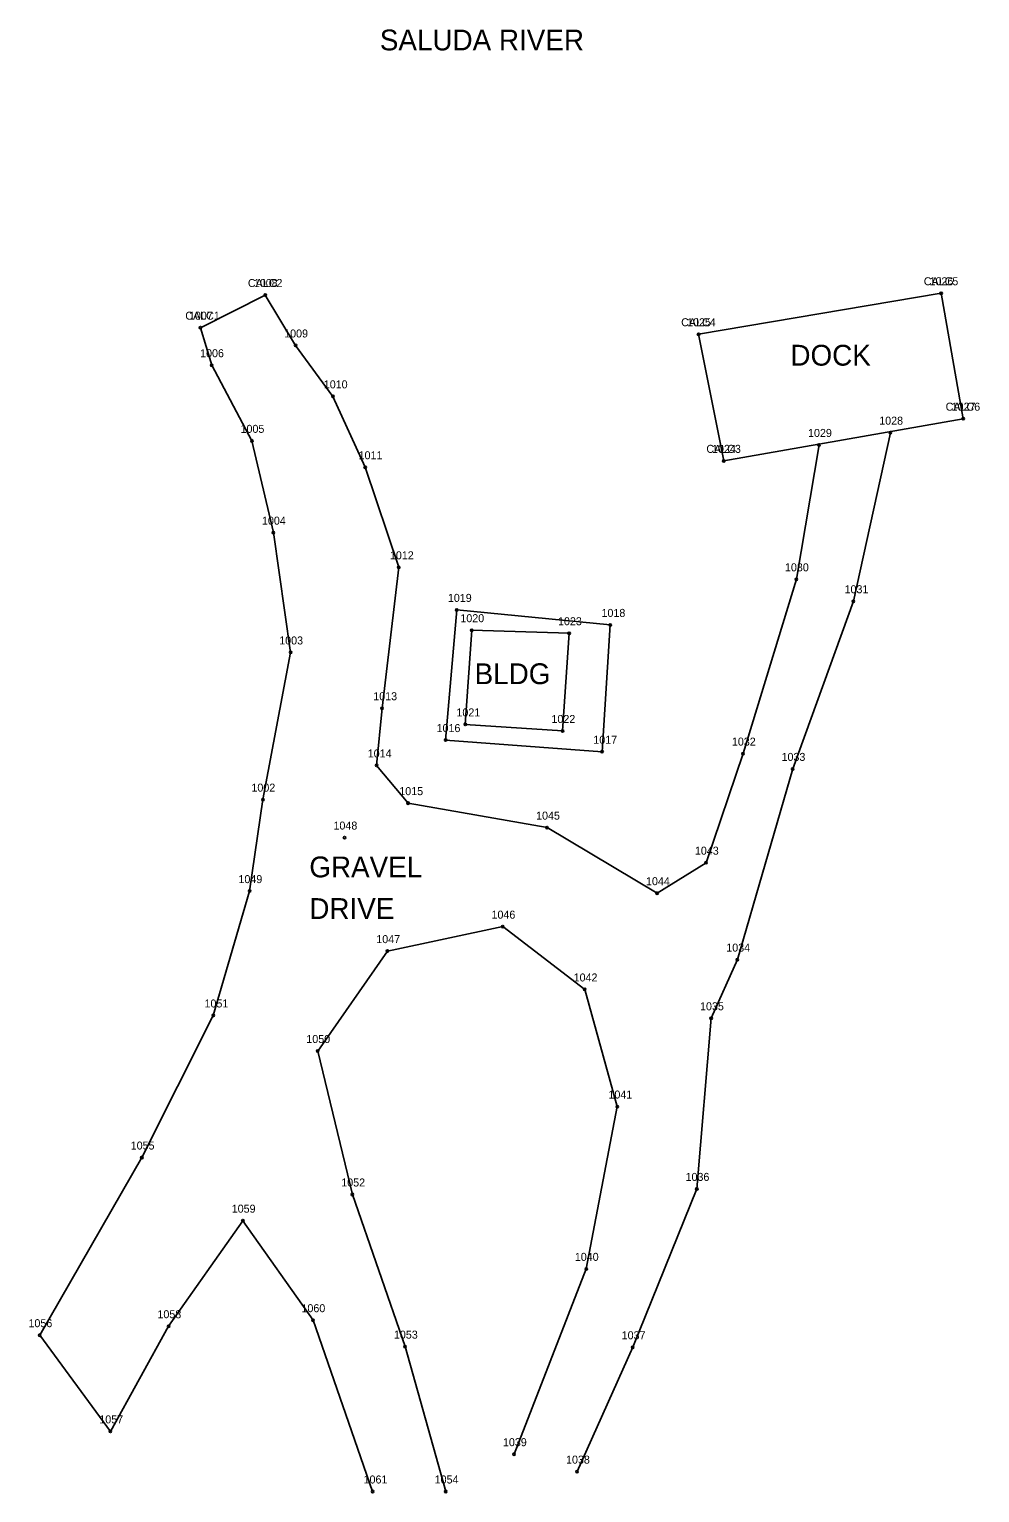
# Model space of a CAD drawing. Extents: x 1968123 to 1968241, y 796379 to 796709.
# Drawn here: x 1968122.5 to 1968241.2, y 796525.7 to 796708.5 of the extents above; entities that cross this region are included whole.
import ezdxf

# ---------------------------------------------------------------- set-up
doc = ezdxf.new("R2010")
doc.units = 0
for name, color, linetype in [('RD_EX_Bldg', 7, 'Continuous'), ('RD_EX_Bldg_txCode', 7, 'Continuous'), ('RD_EX_Driveway', 7, 'Continuous'), ('RD_EX_Driveway_txCode', 7, 'Continuous'), ('RD_EX_Fence_Other', 7, 'Continuous'), ('RD_EX_Fence_Other_txCode', 7, 'Continuous'), ('RD_EX_Misc', 7, 'Continuous'), ('RD_EX_Misc_txCode', 7, 'Continuous'), ('RD_EX_Road', 7, 'Continuous'), ('RD_EX_Road_txCode', 7, 'Continuous'), ('RD_SMD_Locator', 7, 'Continuous')]:
    doc.layers.add(name, color=color, linetype=linetype)

msp = doc.modelspace()

# ---------------------------------------------------------------- linework, layer by layer
at = {"layer": 'RD_EX_Bldg'}
msp.add_lwpolyline([(1968177.79, 796633.44), (1968176.99, 796621.67), (1968189.14, 796620.85), (1968189.96, 796633.06), (1968177.79, 796633.44)], dxfattribs=at)
at = {"layer": 'RD_EX_Fence_Other'}
msp.add_lwpolyline([(1968174.53, 796619.71), (1968194.08, 796618.25), (1968195.1, 796634.1), (1968175.92, 796635.98), (1968174.53, 796619.71)], dxfattribs=at)
at = {"layer": 'RD_EX_Misc'}
msp.add_line((1968209.27, 796654.6), (1968239.18, 796659.87), dxfattribs=at)
msp.add_lwpolyline([(1968209.27, 796654.6), (1968206.12, 796670.42), (1968236.43, 796675.54), (1968239.18, 796659.87)], dxfattribs=at)
at = {"layer": 'RD_EX_Road'}
for points in [[(1968150.04, 796600.84), (1968151.7, 796612.27), (1968155.17, 796630.66), (1968153.02, 796645.63), (1968150.33, 796657.1), (1968145.31, 796666.55), (1968143.9, 796671.24), (1968152, 796675.32), (1968155.78, 796669.02), (1968160.45, 796662.66), (1968164.48, 796653.8), (1968168.68, 796641.3), (1968166.59, 796623.69), (1968165.91, 796616.54), (1968169.84, 796611.83), (1968187.21, 796608.77)], [(1968230.08, 796658.12), (1968225.46, 796637.06), (1968217.88, 796616.11), (1968210.97, 796592.28), (1968207.7, 796584.95), (1968205.91, 796563.63), (1968197.9, 796543.84), (1968190.95, 796528.3)], [(1968221.18, 796656.59), (1968218.35, 796639.8), (1968211.68, 796618.02), (1968207.06, 796604.39), (1968200.95, 796600.58), (1968187.21, 796608.77)], [(1968150.04, 796600.84), (1968145.51, 796585.3), (1968136.58, 796567.55), (1968123.83, 796545.35), (1968132.65, 796533.33), (1968139.92, 796546.47), (1968149.2, 796559.66), (1968157.97, 796547.22), (1968165.41, 796525.82)], [(1968183.08, 796530.48), (1968192.1, 796553.64), (1968195.97, 796573.92), (1968191.91, 796588.55), (1968181.67, 796596.4), (1968167.26, 796593.34), (1968158.56, 796580.86), (1968162.88, 796562.93), (1968169.46, 796543.92), (1968174.54, 796525.82)]]:
    msp.add_lwpolyline(points, dxfattribs=at)
at = {"layer": 'RD_SMD_Locator'}
for centre in [(1968152, 796675.32), (1968152, 796675.32), (1968236.43, 796675.54), (1968236.43, 796675.54), (1968143.9, 796671.24), (1968143.9, 796671.24), (1968206.12, 796670.42), (1968206.12, 796670.42), (1968155.78, 796669.02), (1968145.31, 796666.55), (1968160.45, 796662.66), (1968239.18, 796659.87), (1968239.18, 796659.87), (1968230.08, 796658.12), (1968150.33, 796657.1), (1968221.18, 796656.59), (1968209.27, 796654.6), (1968209.27, 796654.6), (1968164.48, 796653.8), (1968153.02, 796645.63), (1968168.68, 796641.3), (1968218.35, 796639.8), (1968175.92, 796635.98), (1968225.46, 796637.06), (1968195.1, 796634.1), (1968177.79, 796633.44), (1968189.96, 796633.06), (1968155.17, 796630.66), (1968166.59, 796623.69), (1968176.99, 796621.67), (1968174.53, 796619.71), (1968189.14, 796620.85), (1968194.08, 796618.25), (1968211.68, 796618.02), (1968165.91, 796616.54), (1968217.88, 796616.11), (1968151.7, 796612.27), (1968169.84, 796611.83), (1968187.21, 796608.77), (1968161.9, 796607.53), (1968207.06, 796604.39), (1968150.04, 796600.84), (1968200.95, 796600.58), (1968181.67, 796596.4), (1968167.26, 796593.34), (1968210.97, 796592.28), (1968191.91, 796588.55), (1968145.51, 796585.3), (1968207.7, 796584.95), (1968158.56, 796580.86), (1968195.97, 796573.92), (1968136.58, 796567.55), (1968162.88, 796562.93), (1968205.91, 796563.63), (1968149.2, 796559.66), (1968192.1, 796553.64), (1968139.92, 796546.47), (1968157.97, 796547.22), (1968123.83, 796545.35), (1968169.46, 796543.92), (1968197.9, 796543.84), (1968132.65, 796533.33), (1968183.08, 796530.48), (1968190.95, 796528.3), (1968165.41, 796525.82), (1968174.54, 796525.82)]:
    msp.add_circle(centre, 0.15, dxfattribs=at)

# ---------------------------------------------------------------- texts
at = {"layer": 'RD_EX_Bldg_txCode'}
for s, p in [('1020', (1968176.37, 796634.44)), ('1023', (1968188.57, 796634.06)), ('1021', (1968175.88, 796622.67)), ('1022', (1968187.75, 796621.85))]:
    msp.add_text(s, height=1, dxfattribs=at).set_placement(p)
at = {"layer": 'RD_EX_Driveway'}
for s, p in [('SALUDA RIVER', (1968166.31, 796705.89)), ('DOCK', (1968217.6, 796666.5)), ('BLDG', (1968178.15, 796626.7)), ('GRAVEL', (1968157.5, 796602.56)), ('DRIVE', (1968157.5, 796597.36))]:
    msp.add_text(s, height=2.6, dxfattribs=at).set_placement(p)
at = {"layer": 'RD_EX_Driveway_txCode'}
for s, p in [('CALC5', (1968234.26, 796676.54)), ('CALC4', (1968203.95, 796671.42)), ('CALC6', (1968236.99, 796660.87)), ('CALC3', (1968207.1, 796655.6))]:
    msp.add_text(s, height=1, dxfattribs=at).set_placement(p)
at = {"layer": 'RD_EX_Fence_Other_txCode'}
for s, p in [('1019', (1968174.81, 796636.98)), ('1018', (1968194, 796635.1)), ('1016', (1968173.4, 796620.71)), ('1017', (1968192.98, 796619.25))]:
    msp.add_text(s, height=1, dxfattribs=at).set_placement(p)
at = {"layer": 'RD_EX_Misc_txCode'}
for s, p in [('CALC2', (1968149.83, 796676.32)), ('1026', (1968234.98, 796676.54)), ('CALC1', (1968142.01, 796672.24)), ('1025', (1968204.69, 796671.42)), ('1027', (1968237.74, 796660.87)), ('1024', (1968207.81, 796655.6))]:
    msp.add_text(s, height=1, dxfattribs=at).set_placement(p)
at = {"layer": 'RD_EX_Road_txCode'}
for s, p in [('1008', (1968150.57, 796676.32)), ('1007', (1968142.47, 796672.24)), ('1009', (1968154.36, 796670.02)), ('1006', (1968143.86, 796667.55)), ('1010', (1968159.31, 796663.66)), ('1028', (1968228.69, 796659.12)), ('1005', (1968148.91, 796658.1)), ('1029', (1968219.8, 796657.59)), ('1011', (1968163.66, 796654.8)), ('1004', (1968151.59, 796646.63)), ('1012', (1968167.57, 796642.3)), ('1030', (1968216.92, 796640.8)), ('1031', (1968224.36, 796638.06)), ('1003', (1968153.74, 796631.66)), ('1013', (1968165.49, 796624.69)), ('1032', (1968210.29, 796619.02)), ('1014', (1968164.8, 796617.54)), ('1033', (1968216.49, 796617.11)), ('1002', (1968150.27, 796613.27)), ('1015', (1968168.74, 796612.83)), ('1045', (1968185.83, 796609.77)), ('1048', (1968160.52, 796608.53)), ('1043', (1968205.67, 796605.39)), ('1049', (1968148.65, 796601.84)), ('1044', (1968199.56, 796601.58)), ('1046', (1968180.26, 796597.4)), ('1047', (1968165.87, 796594.34)), ('1034', (1968209.59, 796593.28)), ('1042', (1968190.52, 796589.55)), ('1051', (1968144.41, 796586.3)), ('1035', (1968206.31, 796585.95)), ('1050', (1968157.13, 796581.86)), ('1041', (1968194.87, 796574.92)), ('1055', (1968135.19, 796568.55)), ('1052', (1968161.49, 796563.93)), ('1036', (1968204.5, 796564.63)), ('1059', (1968147.81, 796560.66)), ('1040', (1968190.67, 796554.64)), ('1058', (1968138.53, 796547.47)), ('1060', (1968156.52, 796548.22)), ('1056', (1968122.42, 796546.35)), ('1053', (1968168.07, 796544.92)), ('1037', (1968196.52, 796544.84)), ('1057', (1968131.27, 796534.33)), ('1039', (1968181.69, 796531.48)), ('1038', (1968189.57, 796529.3)), ('1061', (1968164.28, 796526.82)), ('1054', (1968173.16, 796526.82))]:
    msp.add_text(s, height=1, dxfattribs=at).set_placement(p)

doc.saveas('drawing.dxf')
